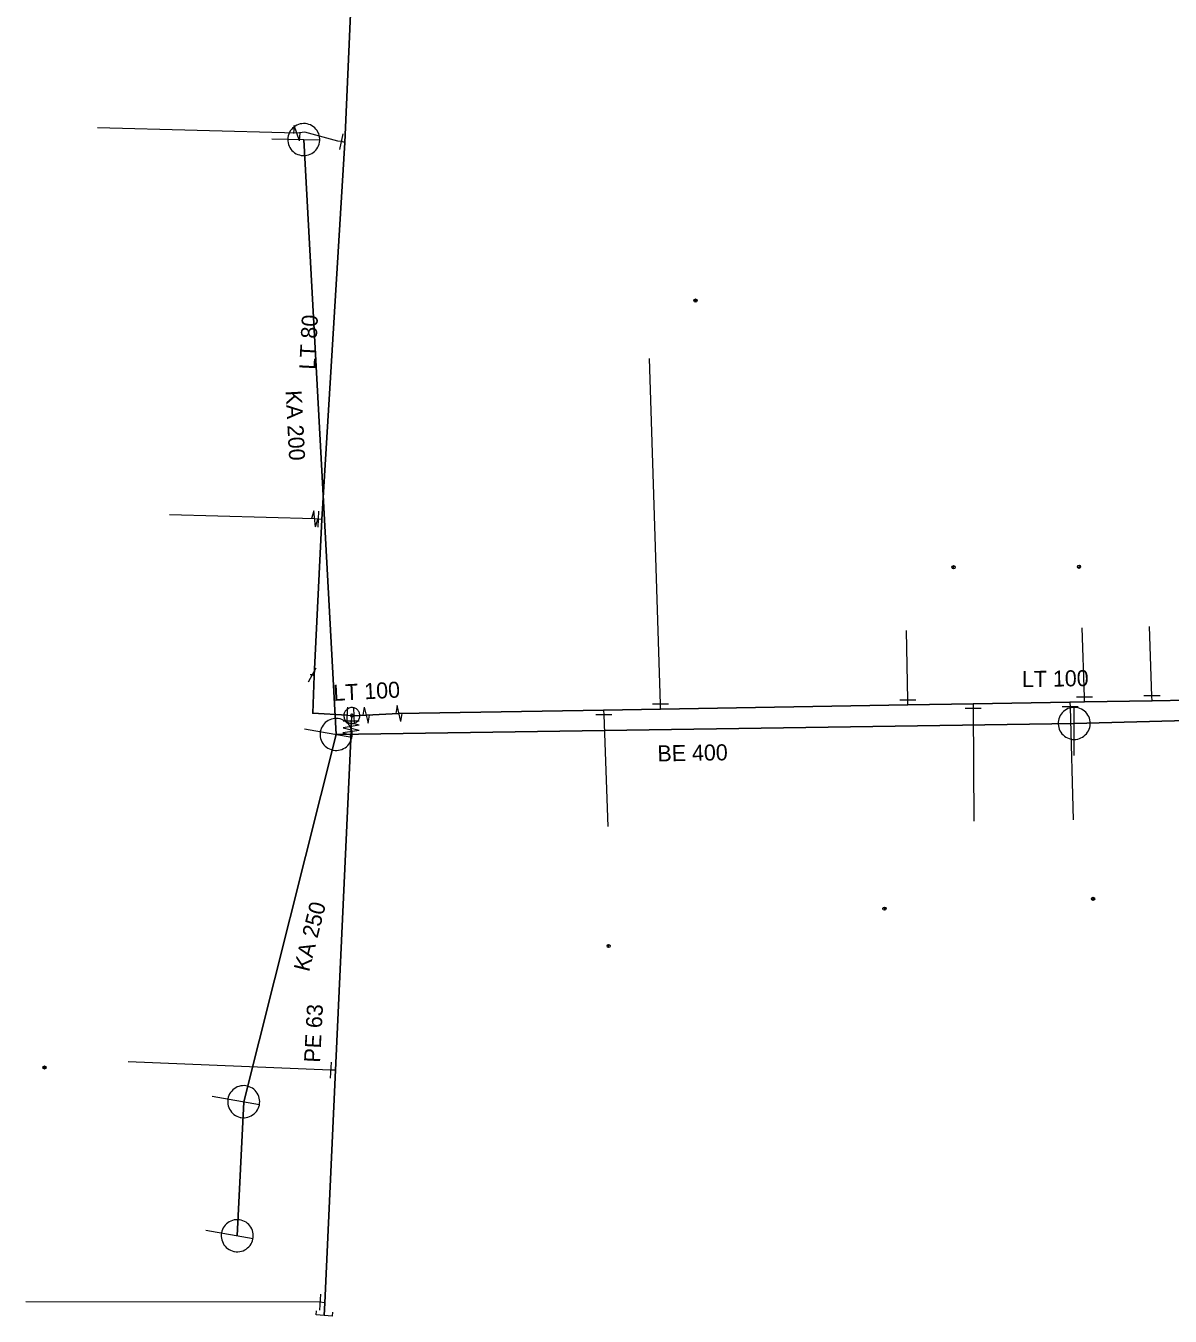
# Model space of a CAD drawing. Extents: x -783064 to -782702, y -1007904 to -1007145.
# Drawn here: x -783046.3 to -782974.9, y -1007592.9 to -1007512.4 of the extents above; entities that cross this region are included whole.
import ezdxf

# ---------------------------------------------------------------- set-up
doc = ezdxf.new("R2010")
doc.units = 0
doc.header["$LTSCALE"] = 0.4
doc.header["$PDMODE"] = 32
doc.header["$PDSIZE"] = 0.2
for name, color, linetype, lineweight in [('1', 7, 'Continuous', 13), ('13', 7, 'Continuous', 13), ('14', 7, 'Continuous', 13), ('17', 7, 'Continuous', 25), ('22', 7, 'Continuous', 13), ('34', 7, 'Continuous', 13), ('47', 7, 'Continuous', 13)]:
    doc.layers.add(name, color=color, linetype=linetype, lineweight=lineweight)

msp = doc.modelspace()

# ---------------------------------------------------------------- linework, layer by layer
at = {"layer": '1'}
for p in [(-783004.5, -1007529.579), (-782988.399, -1007546.209), (-782980.57, -1007546.179), (-782979.69, -1007566.889), (-782992.71, -1007567.499), (-783009.92, -1007569.829), (-783045.12, -1007577.409)]:
    msp.add_point(p, dxfattribs=at)
at = {"layer": '13'}
for p, q in [((-783029.374, -1007519.141), (-783041.817, -1007518.807)), ((-783006.685, -1007554.756), (-783007.37, -1007533.186)), ((-783028.263, -1007543.193), (-783037.312, -1007542.935)), ((-783028.024, -1007543.213), (-783028.263, -1007543.193)), ((-782976.017, -1007554.24), (-782976.174, -1007549.915)), ((-782991.251, -1007554.496), (-782991.339, -1007550.154)), ((-782980.233, -1007554.311), (-782980.383, -1007549.979)), ((-783028.403, -1007552.914), (-783028.541, -1007552.923)), ((-783010.221, -1007555.415), (-783009.967, -1007562.38)), ((-782987.174, -1007555.027), (-782987.132, -1007562.046)), ((-782981.125, -1007554.926), (-782980.933, -1007561.956)), ((-783027.263, -1007577.577), (-783039.891, -1007577.064)), ((-783027.929, -1007592.045), (-783046.285, -1007592.03))]:
    msp.add_line(p, q, dxfattribs=at)
msp.add_lwpolyline([(-783026.588, -1007519.668), (-783026.818, -1007519.639), (-783028.868, -1007519.069), (-783029.374, -1007519.141)], dxfattribs=at)
at = {"layer": '14', "lineweight": 25}
for p, q in [((-783028.94, -1007519.54), (-783026.924, -1007556.637)), ((-782980.87, -1007555.95), (-782939.43, -1007554.87)), ((-783033.09, -1007587.9), (-783032.69, -1007579.54))]:
    msp.add_line(p, q, dxfattribs=at)
at = {"layer": '14'}
for p, q in [((-783026.379, -1007519.715), (-783026.588, -1007519.668)), ((-783027.813, -1007543.224), (-783028.024, -1007543.213)), ((-783028.291, -1007552.975), (-783028.403, -1007552.914)), ((-783006.674, -1007555.056), (-783006.685, -1007554.756)), ((-782991.244, -1007554.796), (-782991.251, -1007554.496)), ((-782987.183, -1007554.728), (-782987.174, -1007555.027)), ((-782981.137, -1007554.626), (-782981.125, -1007554.926)), ((-782980.237, -1007554.611), (-782980.233, -1007554.311)), ((-782976.004, -1007554.539), (-782976.017, -1007554.24)), ((-783026.241, -1007555.437), (-783025.941, -1007555.461)), ((-783025.941, -1007555.461), (-783025.984, -1007555.813)), ((-783025.941, -1007555.461), (-783025.824, -1007555.467)), ((-783010.241, -1007555.116), (-783010.221, -1007555.415)), ((-783026.963, -1007577.576), (-783027.263, -1007577.577)), ((-783027.631, -1007592.077), (-783027.929, -1007592.045))]:
    msp.add_line(p, q, dxfattribs=at)
at = {"layer": '14', "lineweight": 25}
msp.add_lwpolyline([(-783032.69, -1007579.54), (-783026.924, -1007556.637), (-782980.87, -1007555.95)], dxfattribs=at)
at = {"layer": '17'}
for p, q in [((-783025.824, -1007555.467), (-783025.05, -1007555.434)), ((-783025.05, -1007555.434), (-783023.002, -1007555.331)), ((-783025.988, -1007556.14), (-783025.991, -1007556.467)), ((-783025.984, -1007555.813), (-783025.988, -1007556.14))]:
    msp.add_line(p, q, dxfattribs=at)
for points in [[(-783024.585, -1007485.409), (-783024.673, -1007489.846), (-783025.357, -1007496.559), (-783026.379, -1007519.715), (-783027.813, -1007543.224), (-783028.291, -1007552.975), (-783028.377, -1007555.317), (-783026.241, -1007555.437)], [(-782939.219, -1007553.92), (-782948.264, -1007554.072), (-782949.238, -1007554.089), (-782955.049, -1007554.187), (-782959.356, -1007554.259), (-782961.684, -1007554.298), (-782966.33, -1007554.376), (-782973.749, -1007554.501), (-782976.004, -1007554.539), (-782980.237, -1007554.611), (-782981.137, -1007554.626), (-782987.183, -1007554.728), (-782991.244, -1007554.796), (-783006.674, -1007555.056), (-783010.241, -1007555.116), (-783023.002, -1007555.331)], [(-783025.991, -1007556.467), (-783026.963, -1007577.576), (-783027.631, -1007592.077), (-783027.668, -1007592.874)]]:
    msp.add_lwpolyline(points, dxfattribs=at)
at = {"layer": '22'}
for p, q in [((-783030.939, -1007519.493), (-783027.94, -1007519.563)), ((-782980.87, -1007557.95), (-782980.869, -1007554.95)), ((-783028.894, -1007556.289), (-783025.939, -1007556.81)), ((-783034.66, -1007579.192), (-783031.705, -1007579.713)), ((-783035.06, -1007587.552), (-783032.105, -1007588.073))]:
    msp.add_line(p, q, dxfattribs=at)
for points in [[(-783028.963, -1007520.539), (-783028.854, -1007520.536), (-783028.746, -1007520.52), (-783028.639, -1007520.493), (-783028.537, -1007520.455), (-783028.439, -1007520.405), (-783028.348, -1007520.346), (-783028.263, -1007520.275), (-783028.187, -1007520.197), (-783028.119, -1007520.111), (-783028.062, -1007520.018), (-783028.015, -1007519.919), (-783027.979, -1007519.815), (-783027.955, -1007519.709), (-783027.942, -1007519.6), (-783027.942, -1007519.49), (-783027.953, -1007519.381), (-783027.976, -1007519.274), (-783028.01, -1007519.17), (-783028.057, -1007519.071), (-783028.113, -1007518.978), (-783028.18, -1007518.89), (-783028.255, -1007518.811), (-783028.339, -1007518.74), (-783028.43, -1007518.679), (-783028.527, -1007518.629), (-783028.629, -1007518.589), (-783028.735, -1007518.561), (-783028.843, -1007518.544), (-783028.953, -1007518.54), (-783029.062, -1007518.547), (-783029.169, -1007518.566), (-783029.274, -1007518.597), (-783029.375, -1007518.639), (-783029.471, -1007518.692), (-783029.561, -1007518.756), (-783029.643, -1007518.828), (-783029.717, -1007518.909), (-783029.781, -1007518.998), (-783029.835, -1007519.092), (-783029.878, -1007519.194), (-783029.911, -1007519.298), (-783029.931, -1007519.405), (-783029.94, -1007519.515), (-783029.936, -1007519.624), (-783029.921, -1007519.733), (-783029.894, -1007519.838), (-783029.856, -1007519.941), (-783029.806, -1007520.039), (-783029.746, -1007520.131), (-783029.677, -1007520.215), (-783029.599, -1007520.292), (-783029.512, -1007520.359), (-783029.42, -1007520.418), (-783029.321, -1007520.464), (-783029.217, -1007520.5), (-783029.11, -1007520.525), (-783029.001, -1007520.537)], [(-782979.87, -1007555.95), (-782979.875, -1007555.841), (-782979.893, -1007555.733), (-782979.923, -1007555.627), (-782979.963, -1007555.526), (-782980.015, -1007555.429), (-782980.077, -1007555.339), (-782980.149, -1007555.256), (-782980.229, -1007555.182), (-782980.317, -1007555.116), (-782980.411, -1007555.061), (-782980.511, -1007555.016), (-782980.616, -1007554.983), (-782980.723, -1007554.961), (-782980.832, -1007554.951), (-782980.942, -1007554.953), (-782981.05, -1007554.967), (-782981.157, -1007554.992), (-782981.26, -1007555.029), (-782981.358, -1007555.078), (-782981.45, -1007555.136), (-782981.536, -1007555.205), (-782981.613, -1007555.282), (-782981.682, -1007555.368), (-782981.741, -1007555.46), (-782981.789, -1007555.558), (-782981.826, -1007555.661), (-782981.852, -1007555.768), (-782981.866, -1007555.876), (-782981.869, -1007555.986), (-782981.859, -1007556.095), (-782981.838, -1007556.202), (-782981.804, -1007556.306), (-782981.76, -1007556.406), (-782981.705, -1007556.501), (-782981.639, -1007556.589), (-782981.565, -1007556.669), (-782981.482, -1007556.741), (-782981.392, -1007556.803), (-782981.296, -1007556.855), (-782981.194, -1007556.896), (-782981.089, -1007556.926), (-782980.981, -1007556.944), (-782980.871, -1007556.95), (-782980.762, -1007556.944), (-782980.654, -1007556.926), (-782980.549, -1007556.897), (-782980.447, -1007556.856), (-782980.35, -1007556.804), (-782980.26, -1007556.742), (-782980.177, -1007556.671), (-782980.102, -1007556.591), (-782980.037, -1007556.503), (-782979.981, -1007556.409), (-782979.937, -1007556.309), (-782979.903, -1007556.205), (-782979.881, -1007556.097), (-782979.871, -1007555.988)], [(-783027.098, -1007557.621), (-783026.989, -1007557.634), (-783026.88, -1007557.635), (-783026.77, -1007557.624), (-783026.664, -1007557.602), (-783026.559, -1007557.568), (-783026.46, -1007557.522), (-783026.366, -1007557.466), (-783026.279, -1007557.4), (-783026.199, -1007557.325), (-783026.128, -1007557.242), (-783026.066, -1007557.151), (-783026.016, -1007557.053), (-783025.975, -1007556.952), (-783025.947, -1007556.846), (-783025.929, -1007556.738), (-783025.924, -1007556.629), (-783025.931, -1007556.519), (-783025.949, -1007556.411), (-783025.98, -1007556.306), (-783026.021, -1007556.206), (-783026.074, -1007556.109), (-783026.137, -1007556.02), (-783026.21, -1007555.937), (-783026.29, -1007555.863), (-783026.378, -1007555.798), (-783026.473, -1007555.744), (-783026.574, -1007555.7), (-783026.678, -1007555.667), (-783026.786, -1007555.646), (-783026.895, -1007555.637), (-783027.004, -1007555.639), (-783027.112, -1007555.655), (-783027.219, -1007555.681), (-783027.322, -1007555.718), (-783027.42, -1007555.768), (-783027.511, -1007555.827), (-783027.597, -1007555.896), (-783027.673, -1007555.974), (-783027.741, -1007556.06), (-783027.799, -1007556.153), (-783027.847, -1007556.251), (-783027.884, -1007556.354), (-783027.909, -1007556.462), (-783027.922, -1007556.57), (-783027.923, -1007556.68), (-783027.912, -1007556.788), (-783027.89, -1007556.896), (-783027.855, -1007557), (-783027.81, -1007557.1), (-783027.754, -1007557.194), (-783027.689, -1007557.281), (-783027.613, -1007557.361), (-783027.53, -1007557.432), (-783027.44, -1007557.493), (-783027.343, -1007557.544), (-783027.24, -1007557.585), (-783027.135, -1007557.614)], [(-783032.864, -1007580.524), (-783032.755, -1007580.537), (-783032.646, -1007580.538), (-783032.536, -1007580.527), (-783032.43, -1007580.505), (-783032.325, -1007580.471), (-783032.226, -1007580.425), (-783032.132, -1007580.369), (-783032.045, -1007580.303), (-783031.965, -1007580.228), (-783031.894, -1007580.145), (-783031.832, -1007580.054), (-783031.782, -1007579.956), (-783031.741, -1007579.855), (-783031.713, -1007579.749), (-783031.695, -1007579.641), (-783031.69, -1007579.532), (-783031.697, -1007579.422), (-783031.715, -1007579.314), (-783031.746, -1007579.209), (-783031.787, -1007579.109), (-783031.84, -1007579.012), (-783031.903, -1007578.923), (-783031.976, -1007578.84), (-783032.056, -1007578.766), (-783032.144, -1007578.701), (-783032.239, -1007578.647), (-783032.34, -1007578.603), (-783032.444, -1007578.57), (-783032.552, -1007578.549), (-783032.661, -1007578.54), (-783032.77, -1007578.542), (-783032.878, -1007578.558), (-783032.985, -1007578.584), (-783033.088, -1007578.621), (-783033.186, -1007578.671), (-783033.277, -1007578.73), (-783033.363, -1007578.799), (-783033.439, -1007578.877), (-783033.507, -1007578.963), (-783033.565, -1007579.056), (-783033.613, -1007579.154), (-783033.65, -1007579.257), (-783033.675, -1007579.365), (-783033.688, -1007579.473), (-783033.689, -1007579.583), (-783033.678, -1007579.691), (-783033.656, -1007579.799), (-783033.621, -1007579.903), (-783033.576, -1007580.003), (-783033.52, -1007580.097), (-783033.455, -1007580.184), (-783033.379, -1007580.264), (-783033.296, -1007580.335), (-783033.206, -1007580.396), (-783033.109, -1007580.447), (-783033.006, -1007580.488), (-783032.901, -1007580.517)], [(-783033.264, -1007588.884), (-783033.155, -1007588.897), (-783033.046, -1007588.898), (-783032.936, -1007588.887), (-783032.83, -1007588.865), (-783032.725, -1007588.831), (-783032.626, -1007588.785), (-783032.532, -1007588.729), (-783032.445, -1007588.663), (-783032.365, -1007588.588), (-783032.294, -1007588.505), (-783032.232, -1007588.414), (-783032.182, -1007588.316), (-783032.141, -1007588.215), (-783032.113, -1007588.109), (-783032.095, -1007588.001), (-783032.09, -1007587.892), (-783032.097, -1007587.782), (-783032.115, -1007587.674), (-783032.146, -1007587.569), (-783032.187, -1007587.469), (-783032.24, -1007587.372), (-783032.303, -1007587.283), (-783032.376, -1007587.2), (-783032.456, -1007587.126), (-783032.544, -1007587.061), (-783032.639, -1007587.007), (-783032.74, -1007586.963), (-783032.844, -1007586.93), (-783032.952, -1007586.909), (-783033.061, -1007586.9), (-783033.17, -1007586.902), (-783033.278, -1007586.918), (-783033.385, -1007586.944), (-783033.488, -1007586.981), (-783033.586, -1007587.031), (-783033.677, -1007587.09), (-783033.763, -1007587.159), (-783033.839, -1007587.237), (-783033.907, -1007587.323), (-783033.965, -1007587.416), (-783034.013, -1007587.514), (-783034.05, -1007587.617), (-783034.075, -1007587.725), (-783034.088, -1007587.833), (-783034.089, -1007587.943), (-783034.078, -1007588.051), (-783034.056, -1007588.159), (-783034.021, -1007588.263), (-783033.976, -1007588.363), (-783033.92, -1007588.457), (-783033.855, -1007588.544), (-783033.779, -1007588.624), (-783033.696, -1007588.695), (-783033.606, -1007588.756), (-783033.509, -1007588.807), (-783033.406, -1007588.848), (-783033.301, -1007588.877)]]:
    msp.add_lwpolyline(points, close=True, dxfattribs=at)
at = {"layer": '34'}
for p, q in [((-783026.697, -1007520.155), (-783026.477, -1007519.18)), ((-783028.049, -1007543.712), (-783027.997, -1007542.713)), ((-783028.641, -1007553.353), (-783028.163, -1007552.475)), ((-783006.185, -1007554.755), (-783007.185, -1007554.755)), ((-782990.751, -1007554.495), (-782991.751, -1007554.495)), ((-782979.733, -1007554.31), (-782980.733, -1007554.31)), ((-782975.517, -1007554.239), (-782976.517, -1007554.239)), ((-783026.213, -1007554.937), (-783026.269, -1007555.936)), ((-783025.845, -1007554.967), (-783025.803, -1007555.966)), ((-783009.721, -1007555.414), (-783010.721, -1007555.414)), ((-782986.674, -1007555.023), (-782987.673, -1007555.029)), ((-782980.625, -1007554.925), (-782981.625, -1007554.925)), ((-783025.484, -1007555.818), (-783026.483, -1007555.806)), ((-783027.227, -1007577.078), (-783027.299, -1007578.075)), ((-783027.893, -1007591.546), (-783027.965, -1007592.543))]:
    msp.add_line(p, q, dxfattribs=at)
at = {"layer": '47'}
for p, q in [((-783029.206, -1007519.622), (-783029.175, -1007519.112)), ((-783028.207, -1007543.699), (-783028.062, -1007543.209)), ((-783025.169, -1007554.938), (-783025.25, -1007555.442)), ((-783022.881, -1007555.826), (-783022.801, -1007555.322)), ((-783025.486, -1007556.048), (-783025.985, -1007555.939)), ((-783025.487, -1007556.392), (-783025.981, -1007556.266))]:
    msp.add_line(p, q, dxfattribs=at)
for points in [[(-783029.206, -1007519.622), (-783029.541, -1007518.659), (-783029.572, -1007519.169)], [(-783028.207, -1007543.699), (-783028.318, -1007542.686), (-783028.463, -1007543.176)], [(-783025.169, -1007554.938), (-783024.93, -1007555.929), (-783024.849, -1007555.425)], [(-783022.881, -1007555.826), (-783023.122, -1007554.835), (-783023.202, -1007555.339)], [(-783025.486, -1007556.048), (-783026.489, -1007556.231), (-783025.99, -1007556.34)], [(-783025.487, -1007556.392), (-783026.494, -1007556.541), (-783026, -1007556.667)], [(-783027.151, -1007592.666), (-783027.173, -1007592.917), (-783028.162, -1007592.83), (-783028.14, -1007592.579)]]:
    msp.add_lwpolyline(points, dxfattribs=at)
for points in [[(-783025.442, -1007555.5), (-783025.441, -1007555.448), (-783025.445, -1007555.396), (-783025.455, -1007555.345), (-783025.469, -1007555.294), (-783025.489, -1007555.246), (-783025.514, -1007555.2), (-783025.544, -1007555.157), (-783025.578, -1007555.117), (-783025.615, -1007555.081), (-783025.657, -1007555.049), (-783025.702, -1007555.021), (-783025.749, -1007554.999), (-783025.798, -1007554.981), (-783025.849, -1007554.969), (-783025.901, -1007554.962), (-783025.953, -1007554.961), (-783026.005, -1007554.965), (-783026.057, -1007554.975), (-783026.107, -1007554.989), (-783026.155, -1007555.009), (-783026.201, -1007555.034), (-783026.245, -1007555.064), (-783026.285, -1007555.098), (-783026.321, -1007555.135), (-783026.352, -1007555.177), (-783026.38, -1007555.222), (-783026.403, -1007555.269), (-783026.42, -1007555.318), (-783026.432, -1007555.369), (-783026.439, -1007555.421), (-783026.44, -1007555.473), (-783026.436, -1007555.525), (-783026.427, -1007555.577), (-783026.412, -1007555.627), (-783026.392, -1007555.675), (-783026.368, -1007555.721), (-783026.338, -1007555.765), (-783026.304, -1007555.805), (-783026.266, -1007555.841), (-783026.224, -1007555.872), (-783026.179, -1007555.9), (-783026.133, -1007555.923), (-783026.083, -1007555.94), (-783026.032, -1007555.952), (-783025.98, -1007555.959), (-783025.928, -1007555.96), (-783025.876, -1007555.956), (-783025.825, -1007555.947), (-783025.774, -1007555.932), (-783025.726, -1007555.912), (-783025.68, -1007555.888), (-783025.637, -1007555.858), (-783025.597, -1007555.824), (-783025.561, -1007555.786), (-783025.529, -1007555.744), (-783025.501, -1007555.699), (-783025.479, -1007555.653), (-783025.461, -1007555.603), (-783025.449, -1007555.552)], [(-783025.859, -1007555.467), (-783025.858, -1007555.458), (-783025.859, -1007555.45), (-783025.861, -1007555.442), (-783025.863, -1007555.434), (-783025.866, -1007555.425), (-783025.871, -1007555.418), (-783025.875, -1007555.411), (-783025.881, -1007555.404), (-783025.887, -1007555.399), (-783025.894, -1007555.393), (-783025.902, -1007555.388), (-783025.909, -1007555.385), (-783025.917, -1007555.382), (-783025.925, -1007555.379), (-783025.934, -1007555.379), (-783025.943, -1007555.378), (-783025.951, -1007555.379), (-783025.959, -1007555.381), (-783025.967, -1007555.383), (-783025.976, -1007555.386), (-783025.983, -1007555.391), (-783025.99, -1007555.395), (-783025.997, -1007555.401), (-783026.003, -1007555.407), (-783026.008, -1007555.414), (-783026.013, -1007555.422), (-783026.016, -1007555.429), (-783026.019, -1007555.437), (-783026.022, -1007555.445), (-783026.022, -1007555.454), (-783026.023, -1007555.463), (-783026.022, -1007555.471), (-783026.02, -1007555.479), (-783026.018, -1007555.487), (-783026.015, -1007555.496), (-783026.011, -1007555.503), (-783026.006, -1007555.51), (-783026, -1007555.517), (-783025.994, -1007555.523), (-783025.987, -1007555.528), (-783025.979, -1007555.533), (-783025.972, -1007555.536), (-783025.964, -1007555.539), (-783025.956, -1007555.542), (-783025.947, -1007555.542), (-783025.938, -1007555.543), (-783025.93, -1007555.542), (-783025.922, -1007555.54), (-783025.914, -1007555.538), (-783025.905, -1007555.535), (-783025.898, -1007555.531), (-783025.891, -1007555.526), (-783025.884, -1007555.52), (-783025.879, -1007555.514), (-783025.873, -1007555.507), (-783025.868, -1007555.499), (-783025.865, -1007555.492), (-783025.862, -1007555.484), (-783025.859, -1007555.476)]]:
    msp.add_lwpolyline(points, close=True, dxfattribs=at)

# ---------------------------------------------------------------- texts
at = {"layer": '1'}
for s, rotation, p in [('LT 80 ', 87, (-783028.232, -1007533.904)), ('KA 200', 273, (-783030.077, -1007535.2)), ('LT 100', 1, (-782984.126, -1007553.69)), ('LT 100', 3, (-783027.071, -1007554.549)), ('BE 400', 1, (-783006.867, -1007558.323)), ('KA 250', 76, (-783028.613, -1007571.482)), ('PE 63 ', 87, (-783027.928, -1007577.122))]:
    msp.add_text(s, height=1, rotation=rotation, dxfattribs=at).set_placement(p)

doc.saveas('drawing.dxf')
